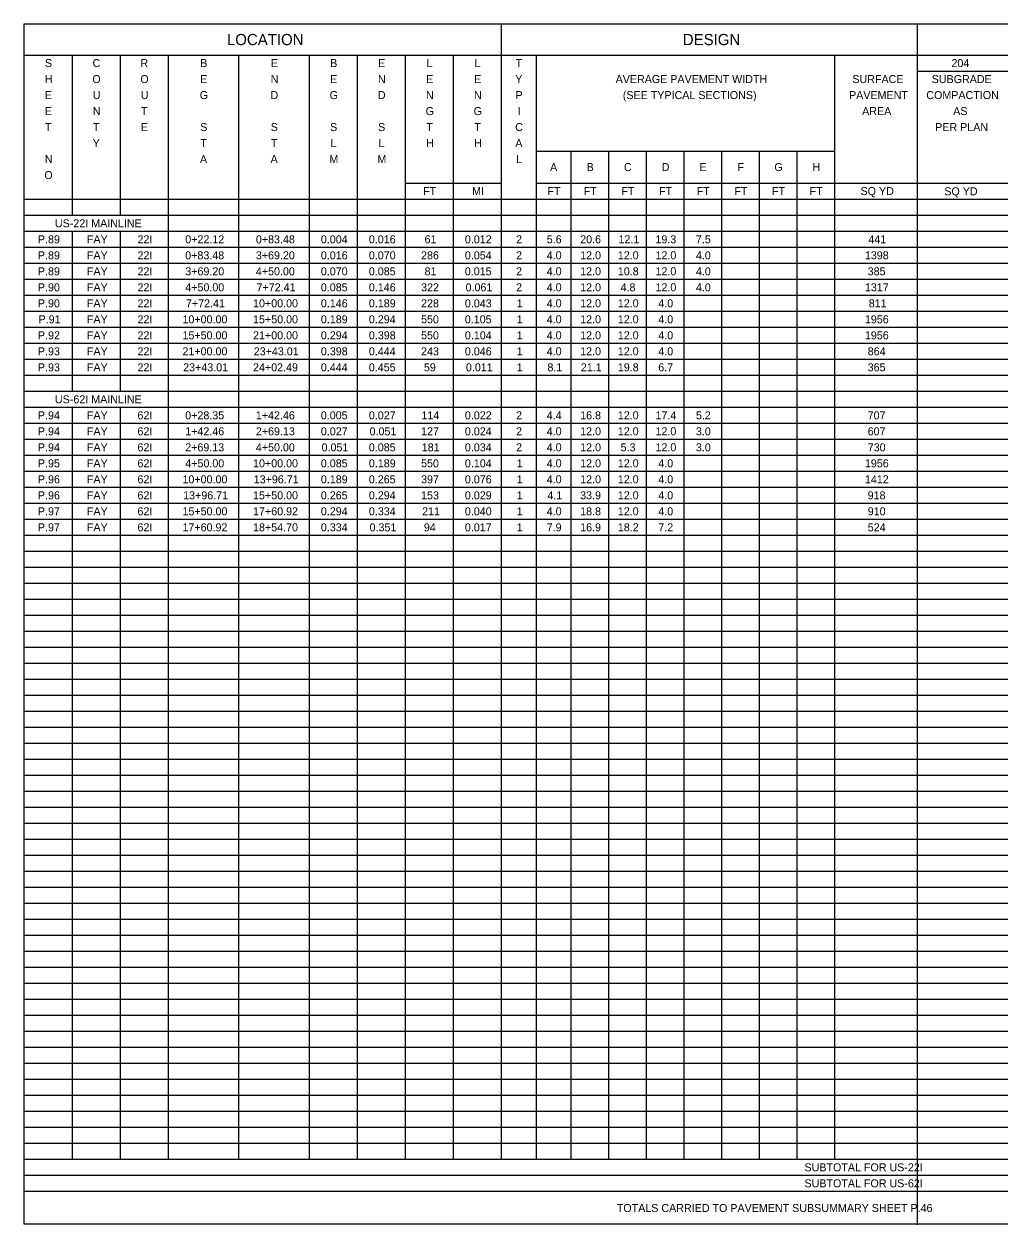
# Model space of a CAD drawing. Extents: x 12522 to 13018, y 1124 to 1902.
# Drawn here: x 12797.22 to 12814.3, y 1708.07 to 1729.09 of the extents above; entities that cross this region are included whole.
import ezdxf

# ---------------------------------------------------------------- set-up
doc = ezdxf.new("R2010")
doc.units = 0
for name, color, linetype in [('SC_Scratch1', 7, 'Continuous'), ('SH_Data', 7, 'Continuous'), ('SH_Text', 7, 'Continuous')]:
    doc.layers.add(name, color=color, linetype=linetype)

msp = doc.modelspace()

# ---------------------------------------------------------------- linework, layer by layer
at = {"layer": 'SC_Scratch1'}
msp.add_lwpolyline([(12797.224, 1729.086), (12827.724, 1729.086), (12827.724, 1708.086), (12797.224, 1708.086)], close=True, dxfattribs=at)
at = {"layer": 'SH_Data'}
for p, q in [((12805.575, 1729.086), (12805.575, 1709.222)), ((12812.855, 1729.086), (12812.855, 1708.069)), ((12797.224, 1728.542), (12827.678, 1728.542)), ((12798.064, 1728.542), (12798.064, 1725.742)), ((12798.904, 1728.542), (12798.904, 1725.742)), ((12799.744, 1728.542), (12799.744, 1709.222)), ((12800.979, 1728.542), (12800.979, 1709.222)), ((12802.215, 1728.542), (12802.215, 1709.222)), ((12803.055, 1728.542), (12803.055, 1709.222)), ((12803.895, 1728.542), (12803.895, 1709.222)), ((12804.735, 1728.542), (12804.735, 1709.222)), ((12806.184, 1728.542), (12806.184, 1709.222)), ((12811.405, 1728.542), (12811.405, 1709.222)), ((12812.855, 1728.262), (12827.678, 1728.262)), ((12806.184, 1726.862), (12811.405, 1726.862)), ((12806.794, 1726.862), (12806.794, 1709.222)), ((12807.452, 1726.862), (12807.452, 1709.222)), ((12808.111, 1726.862), (12808.111, 1709.222)), ((12808.77, 1726.862), (12808.77, 1709.222)), ((12809.429, 1726.862), (12809.429, 1709.222)), ((12810.088, 1726.862), (12810.088, 1709.222)), ((12810.747, 1726.862), (12810.747, 1709.222)), ((12803.895, 1726.302), (12805.575, 1726.302)), ((12806.184, 1726.302), (12827.678, 1726.302)), ((12797.224, 1726.022), (12827.678, 1726.022)), ((12797.224, 1725.742), (12827.678, 1725.742)), ((12797.224, 1725.462), (12827.678, 1725.462)), ((12798.064, 1725.462), (12798.064, 1722.662)), ((12798.904, 1725.462), (12798.904, 1722.662)), ((12797.224, 1725.182), (12827.678, 1725.182)), ((12797.224, 1724.902), (12827.678, 1724.902)), ((12797.224, 1724.622), (12827.678, 1724.622)), ((12797.224, 1724.342), (12827.678, 1724.342)), ((12797.224, 1724.062), (12827.678, 1724.062)), ((12797.224, 1723.782), (12827.678, 1723.782)), ((12797.224, 1723.502), (12827.678, 1723.502)), ((12797.224, 1723.222), (12827.678, 1723.222)), ((12797.224, 1722.942), (12827.678, 1722.942)), ((12797.224, 1722.662), (12827.678, 1722.662)), ((12797.224, 1722.382), (12827.678, 1722.382)), ((12798.064, 1722.382), (12798.064, 1709.222)), ((12798.904, 1722.382), (12798.904, 1709.222)), ((12797.224, 1722.102), (12827.678, 1722.102)), ((12797.224, 1721.822), (12827.678, 1721.822)), ((12797.224, 1721.542), (12827.678, 1721.542)), ((12797.224, 1721.262), (12827.678, 1721.262)), ((12797.224, 1720.982), (12827.678, 1720.982)), ((12797.224, 1720.702), (12827.678, 1720.702)), ((12797.224, 1720.422), (12827.678, 1720.422)), ((12797.224, 1720.142), (12827.678, 1720.142)), ((12797.224, 1719.862), (12827.678, 1719.862)), ((12797.224, 1719.582), (12827.678, 1719.582)), ((12797.224, 1719.302), (12827.678, 1719.302)), ((12797.224, 1719.022), (12827.678, 1719.022)), ((12797.224, 1718.742), (12827.678, 1718.742)), ((12797.224, 1718.462), (12827.678, 1718.462)), ((12797.224, 1718.182), (12827.678, 1718.182)), ((12797.224, 1717.902), (12827.678, 1717.902)), ((12797.224, 1717.622), (12827.678, 1717.622)), ((12797.224, 1717.342), (12827.678, 1717.342)), ((12797.224, 1717.062), (12827.678, 1717.062)), ((12797.224, 1716.782), (12827.678, 1716.782)), ((12797.224, 1716.502), (12827.678, 1716.502)), ((12797.224, 1716.222), (12827.678, 1716.222)), ((12797.224, 1715.942), (12827.678, 1715.942)), ((12797.224, 1715.662), (12827.678, 1715.662)), ((12797.224, 1715.382), (12827.678, 1715.382)), ((12797.224, 1715.102), (12827.678, 1715.102)), ((12797.224, 1714.822), (12827.678, 1714.822)), ((12797.224, 1714.542), (12827.678, 1714.542)), ((12797.224, 1714.262), (12827.678, 1714.262)), ((12797.224, 1713.982), (12827.678, 1713.982)), ((12797.224, 1713.702), (12827.678, 1713.702)), ((12797.224, 1713.422), (12827.678, 1713.422)), ((12797.224, 1713.142), (12827.678, 1713.142)), ((12797.224, 1712.862), (12827.678, 1712.862)), ((12797.224, 1712.582), (12827.678, 1712.582)), ((12797.224, 1712.302), (12827.678, 1712.302)), ((12797.224, 1712.022), (12827.678, 1712.022)), ((12797.224, 1711.742), (12827.678, 1711.742)), ((12797.224, 1711.462), (12827.678, 1711.462)), ((12797.224, 1711.182), (12827.678, 1711.182)), ((12797.224, 1710.902), (12827.678, 1710.902)), ((12797.224, 1710.622), (12827.678, 1710.622)), ((12797.224, 1710.342), (12827.678, 1710.342)), ((12797.224, 1710.062), (12827.678, 1710.062)), ((12797.224, 1709.782), (12827.678, 1709.782)), ((12797.224, 1709.502), (12827.678, 1709.502)), ((12797.224, 1709.222), (12827.678, 1709.222)), ((12797.224, 1708.942), (12827.678, 1708.942)), ((12797.224, 1708.662), (12827.678, 1708.662))]:
    msp.add_line(p, q, dxfattribs=at)

# ---------------------------------------------------------------- texts
at = {"layer": 'SH_Text'}
for s, height, p in [('LOCATION', 0.196, (12800.775, 1728.716)), ('DESIGN', 0.196, (12808.752, 1728.716)), ('S', 0.14, (12797.59, 1728.332)), ('C', 0.14, (12798.424, 1728.332)), ('R', 0.14, (12799.262, 1728.332)), ('B', 0.14, (12800.308, 1728.332)), ('E', 0.14, (12801.543, 1728.332)), ('B', 0.14, (12802.581, 1728.332)), ('E', 0.14, (12803.421, 1728.332)), ('L', 0.14, (12804.269, 1728.332)), ('L', 0.14, (12805.109, 1728.332)), ('T', 0.14, (12805.827, 1728.332)), ('204', 0.14, (12813.453, 1728.332)), ('H', 0.14, (12797.588, 1728.052)), ('O', 0.14, (12798.42, 1728.052)), ('O', 0.14, (12799.26, 1728.052)), ('E', 0.14, (12800.308, 1728.052)), ('N', 0.14, (12801.541, 1728.052)), ('E', 0.14, (12802.581, 1728.052)), ('N', 0.14, (12803.418, 1728.052)), ('E', 0.14, (12804.261, 1728.052)), ('E', 0.14, (12805.101, 1728.052)), ('Y', 0.14, (12805.821, 1728.052)), ('AVERAGE PAVEMENT WIDTH', 0.14, (12807.576, 1728.052)), ('SURFACE', 0.14, (12811.719, 1728.052)), ('SUBGRADE', 0.14, (12813.107, 1728.052)), ('E', 0.14, (12797.59, 1727.772)), ('U', 0.14, (12798.428, 1727.772)), ('U', 0.14, (12799.268, 1727.772)), ('G', 0.14, (12800.299, 1727.772)), ('D', 0.14, (12801.538, 1727.772)), ('G', 0.14, (12802.572, 1727.772)), ('D', 0.14, (12803.416, 1727.772)), ('N', 0.14, (12804.258, 1727.772)), ('N', 0.14, (12805.098, 1727.772)), ('P', 0.14, (12805.825, 1727.772)), ('(SEE TYPICAL SECTIONS)', 0.14, (12807.702, 1727.772)), ('PAVEMENT', 0.14, (12811.661, 1727.772)), ('COMPACTION', 0.14, (12813.013, 1727.772)), ('E', 0.14, (12797.59, 1727.492)), ('N', 0.14, (12798.428, 1727.492)), ('T', 0.14, (12799.272, 1727.492)), ('G', 0.14, (12804.252, 1727.492)), ('G', 0.14, (12805.092, 1727.492)), ('I', 0.14, (12805.863, 1727.492)), ('AREA', 0.14, (12811.89, 1727.492)), ('AS', 0.14, (12813.483, 1727.492)), ('T', 0.14, (12797.592, 1727.212)), ('T', 0.14, (12798.432, 1727.212)), ('E', 0.14, (12799.27, 1727.212)), ('S', 0.14, (12800.308, 1727.212)), ('S', 0.14, (12801.543, 1727.212)), ('S', 0.14, (12802.581, 1727.212)), ('S', 0.14, (12803.421, 1727.212)), ('T', 0.14, (12804.263, 1727.212)), ('T', 0.14, (12805.103, 1727.212)), ('C', 0.14, (12805.819, 1727.212)), ('PER PLAN', 0.14, (12813.168, 1727.212)), ('Y', 0.14, (12798.426, 1726.932)), ('T', 0.14, (12800.31, 1726.932)), ('T', 0.14, (12801.545, 1726.932)), ('L', 0.14, (12802.589, 1726.932)), ('L', 0.14, (12803.429, 1726.932)), ('H', 0.14, (12804.258, 1726.932)), ('H', 0.14, (12805.098, 1726.932)), ('A', 0.14, (12805.821, 1726.932)), ('N', 0.14, (12797.588, 1726.652)), ('A', 0.14, (12800.303, 1726.652)), ('A', 0.14, (12801.538, 1726.652)), ('M', 0.14, (12802.568, 1726.652)), ('M', 0.14, (12803.408, 1726.652)), ('L', 0.14, (12805.834, 1726.652)), ('O', 0.14, (12797.58, 1726.372)), ('A', 0.14, (12806.43, 1726.512)), ('B', 0.14, (12807.069, 1726.512)), ('C', 0.14, (12807.722, 1726.512)), ('D', 0.14, (12808.382, 1726.512)), ('E', 0.14, (12809.045, 1726.512)), ('F', 0.14, (12809.709, 1726.512)), ('G', 0.14, (12810.354, 1726.512)), ('H', 0.14, (12811.02, 1726.512)), ('FT', 0.14, (12804.209, 1726.092)), ('MI', 0.14, (12805.065, 1726.092)), ('FT', 0.14, (12806.383, 1726.092)), ('FT', 0.14, (12807.017, 1726.092)), ('FT', 0.14, (12807.676, 1726.092)), ('FT', 0.14, (12808.335, 1726.092)), ('FT', 0.14, (12808.994, 1726.092)), ('FT', 0.14, (12809.653, 1726.092)), ('FT', 0.14, (12810.311, 1726.092)), ('FT', 0.14, (12810.97, 1726.092)), ('SQ YD', 0.14, (12811.862, 1726.092)), ('SQ YD', 0.14, (12813.328, 1726.088)), ('US-22I MAINLINE', 0.14, (12797.765, 1725.528)), ('P.89', 0.14, (12797.467, 1725.248)), ('FAY', 0.14, (12798.325, 1725.248)), ('22I', 0.14, (12799.21, 1725.248)), ('0+22.12', 0.14, (12800.046, 1725.248)), ('0+83.48', 0.14, (12801.281, 1725.248)), ('0.004', 0.14, (12802.419, 1725.248)), ('0.016', 0.14, (12803.259, 1725.248)), ('61', 0.14, (12804.233, 1725.248)), ('0.012', 0.14, (12804.939, 1725.248)), ('2', 0.14, (12805.835, 1725.248)), ('5.6', 0.14, (12806.371, 1725.248)), ('20.6', 0.14, (12806.956, 1725.248)), ('12.1', 0.14, (12807.627, 1725.248)), ('19.3', 0.14, (12808.273, 1725.248)), ('7.5', 0.14, (12808.981, 1725.248)), ('441', 0.14, (12811.999, 1725.248)), ('P.89', 0.14, (12797.467, 1724.968)), ('FAY', 0.14, (12798.325, 1724.968)), ('22I', 0.14, (12799.21, 1724.968)), ('0+83.48', 0.14, (12800.045, 1724.968)), ('3+69.20', 0.14, (12801.281, 1724.968)), ('0.016', 0.14, (12802.419, 1724.968)), ('0.070', 0.14, (12803.259, 1724.968)), ('286', 0.14, (12804.172, 1724.968)), ('0.054', 0.14, (12804.939, 1724.968)), ('2', 0.14, (12805.835, 1724.968)), ('4.0', 0.14, (12806.371, 1724.968)), ('12.0', 0.14, (12806.956, 1724.968)), ('12.0', 0.14, (12807.615, 1724.968)), ('12.0', 0.14, (12808.274, 1724.968)), ('4.0', 0.14, (12808.981, 1724.968)), ('1398', 0.14, (12811.938, 1724.968)), ('P.89', 0.14, (12797.467, 1724.688)), ('FAY', 0.14, (12798.325, 1724.688)), ('22I', 0.14, (12799.21, 1724.688)), ('3+69.20', 0.14, (12800.046, 1724.688)), ('4+50.00', 0.14, (12801.281, 1724.688)), ('0.070', 0.14, (12802.419, 1724.688)), ('0.085', 0.14, (12803.258, 1724.688)), ('81', 0.14, (12804.233, 1724.688)), ('0.015', 0.14, (12804.938, 1724.688)), ('2', 0.14, (12805.835, 1724.688)), ('4.0', 0.14, (12806.371, 1724.688)), ('12.0', 0.14, (12806.956, 1724.688)), ('10.8', 0.14, (12807.615, 1724.688)), ('12.0', 0.14, (12808.274, 1724.688)), ('4.0', 0.14, (12808.981, 1724.688)), ('385', 0.14, (12811.987, 1724.688)), ('P.90', 0.14, (12797.467, 1724.408)), ('FAY', 0.14, (12798.325, 1724.408)), ('22I', 0.14, (12799.21, 1724.408)), ('4+50.00', 0.14, (12800.046, 1724.408)), ('7+72.41', 0.14, (12801.293, 1724.408)), ('0.085', 0.14, (12802.418, 1724.408)), ('0.146', 0.14, (12803.259, 1724.408)), ('322', 0.14, (12804.173, 1724.408)), ('0.061', 0.14, (12804.951, 1724.408)), ('2', 0.14, (12805.835, 1724.408)), ('4.0', 0.14, (12806.371, 1724.408)), ('12.0', 0.14, (12806.956, 1724.408)), ('4.8', 0.14, (12807.663, 1724.408)), ('12.0', 0.14, (12808.274, 1724.408)), ('4.0', 0.14, (12808.981, 1724.408)), ('1317', 0.14, (12811.938, 1724.408)), ('P.90', 0.14, (12797.467, 1724.128)), ('FAY', 0.14, (12798.325, 1724.128)), ('22I', 0.14, (12799.21, 1724.128)), ('7+72.41', 0.14, (12800.058, 1724.128)), ('10+00.00', 0.14, (12801.232, 1724.128)), ('0.146', 0.14, (12802.419, 1724.128)), ('0.189', 0.14, (12803.259, 1724.128)), ('228', 0.14, (12804.172, 1724.128)), ('0.043', 0.14, (12804.939, 1724.128)), ('1', 0.14, (12805.847, 1724.128)), ('4.0', 0.14, (12806.371, 1724.128)), ('12.0', 0.14, (12806.956, 1724.128)), ('12.0', 0.14, (12807.615, 1724.128)), ('4.0', 0.14, (12808.323, 1724.128)), ('811', 0.14, (12812.006, 1724.128)), ('P.91', 0.14, (12797.479, 1723.848)), ('FAY', 0.14, (12798.325, 1723.848)), ('22I', 0.14, (12799.21, 1723.848)), ('10+00.00', 0.14, (12799.997, 1723.848)), ('15+50.00', 0.14, (12801.232, 1723.848)), ('0.189', 0.14, (12802.419, 1723.848)), ('0.294', 0.14, (12803.259, 1723.848)), ('550', 0.14, (12804.172, 1723.848)), ('0.105', 0.14, (12804.938, 1723.848)), ('1', 0.14, (12805.847, 1723.848)), ('4.0', 0.14, (12806.371, 1723.848)), ('12.0', 0.14, (12806.956, 1723.848)), ('12.0', 0.14, (12807.615, 1723.848)), ('4.0', 0.14, (12808.323, 1723.848)), ('1956', 0.14, (12811.938, 1723.848)), ('P.92', 0.14, (12797.468, 1723.568)), ('FAY', 0.14, (12798.325, 1723.568)), ('22I', 0.14, (12799.21, 1723.568)), ('15+50.00', 0.14, (12799.997, 1723.568)), ('21+00.00', 0.14, (12801.232, 1723.568)), ('0.294', 0.14, (12802.419, 1723.568)), ('0.398', 0.14, (12803.259, 1723.568)), ('550', 0.14, (12804.172, 1723.568)), ('0.104', 0.14, (12804.939, 1723.568)), ('1', 0.14, (12805.847, 1723.568)), ('4.0', 0.14, (12806.371, 1723.568)), ('12.0', 0.14, (12806.956, 1723.568)), ('12.0', 0.14, (12807.615, 1723.568)), ('4.0', 0.14, (12808.323, 1723.568)), ('1956', 0.14, (12811.938, 1723.568)), ('P.93', 0.14, (12797.467, 1723.288)), ('FAY', 0.14, (12798.325, 1723.288)), ('22I', 0.14, (12799.21, 1723.288)), ('21+00.00', 0.14, (12799.997, 1723.288)), ('23+43.01', 0.14, (12801.244, 1723.288)), ('0.398', 0.14, (12802.419, 1723.288)), ('0.444', 0.14, (12803.259, 1723.288)), ('243', 0.14, (12804.172, 1723.288)), ('0.046', 0.14, (12804.939, 1723.288)), ('1', 0.14, (12805.847, 1723.288)), ('4.0', 0.14, (12806.371, 1723.288)), ('12.0', 0.14, (12806.956, 1723.288)), ('12.0', 0.14, (12807.615, 1723.288)), ('4.0', 0.14, (12808.323, 1723.288)), ('864', 0.14, (12811.988, 1723.288)), ('P.93', 0.14, (12797.467, 1723.008)), ('FAY', 0.14, (12798.325, 1723.008)), ('22I', 0.14, (12799.21, 1723.008)), ('23+43.01', 0.14, (12800.009, 1723.008)), ('24+02.49', 0.14, (12801.232, 1723.008)), ('0.444', 0.14, (12802.419, 1723.008)), ('0.455', 0.14, (12803.258, 1723.008)), ('59', 0.14, (12804.221, 1723.008)), ('0.011', 0.14, (12804.957, 1723.008)), ('1', 0.14, (12805.847, 1723.008)), ('8.1', 0.14, (12806.383, 1723.008)), ('21.1', 0.14, (12806.968, 1723.008)), ('19.8', 0.14, (12807.615, 1723.008)), ('6.7', 0.14, (12808.322, 1723.008)), ('365', 0.14, (12811.987, 1723.008)), ('US-62I MAINLINE', 0.14, (12797.765, 1722.448)), ('P.94', 0.14, (12797.467, 1722.168)), ('FAY', 0.14, (12798.325, 1722.168)), ('62I', 0.14, (12799.21, 1722.168)), ('0+28.35', 0.14, (12800.045, 1722.168)), ('1+42.46', 0.14, (12801.281, 1722.168)), ('0.005', 0.14, (12802.418, 1722.168)), ('0.027', 0.14, (12803.259, 1722.168)), ('114', 0.14, (12804.179, 1722.168)), ('0.022', 0.14, (12804.939, 1722.168)), ('2', 0.14, (12805.835, 1722.168)), ('4.4', 0.14, (12806.371, 1722.168)), ('16.8', 0.14, (12806.956, 1722.168)), ('12.0', 0.14, (12807.615, 1722.168)), ('17.4', 0.14, (12808.274, 1722.168)), ('5.2', 0.14, (12808.982, 1722.168)), ('707', 0.14, (12811.987, 1722.168)), ('P.94', 0.14, (12797.467, 1721.888)), ('FAY', 0.14, (12798.325, 1721.888)), ('62I', 0.14, (12799.21, 1721.888)), ('1+42.46', 0.14, (12800.045, 1721.888)), ('2+69.13', 0.14, (12801.281, 1721.888)), ('0.027', 0.14, (12802.419, 1721.888)), ('0.051', 0.14, (12803.271, 1721.888)), ('127', 0.14, (12804.172, 1721.888)), ('0.024', 0.14, (12804.939, 1721.888)), ('2', 0.14, (12805.835, 1721.888)), ('4.0', 0.14, (12806.371, 1721.888)), ('12.0', 0.14, (12806.956, 1721.888)), ('12.0', 0.14, (12807.615, 1721.888)), ('12.0', 0.14, (12808.274, 1721.888)), ('3.0', 0.14, (12808.981, 1721.888)), ('607', 0.14, (12811.987, 1721.888)), ('P.94', 0.14, (12797.467, 1721.608)), ('FAY', 0.14, (12798.325, 1721.608)), ('62I', 0.14, (12799.21, 1721.608)), ('2+69.13', 0.14, (12800.045, 1721.608)), ('4+50.00', 0.14, (12801.281, 1721.608)), ('0.051', 0.14, (12802.431, 1721.608)), ('0.085', 0.14, (12803.258, 1721.608)), ('181', 0.14, (12804.184, 1721.608)), ('0.034', 0.14, (12804.939, 1721.608)), ('2', 0.14, (12805.835, 1721.608)), ('4.0', 0.14, (12806.371, 1721.608)), ('12.0', 0.14, (12806.956, 1721.608)), ('5.3', 0.14, (12807.664, 1721.608)), ('12.0', 0.14, (12808.274, 1721.608)), ('3.0', 0.14, (12808.981, 1721.608)), ('730', 0.14, (12811.988, 1721.608)), ('P.95', 0.14, (12797.467, 1721.328)), ('FAY', 0.14, (12798.325, 1721.328)), ('62I', 0.14, (12799.21, 1721.328)), ('4+50.00', 0.14, (12800.046, 1721.328)), ('10+00.00', 0.14, (12801.232, 1721.328)), ('0.085', 0.14, (12802.418, 1721.328)), ('0.189', 0.14, (12803.259, 1721.328)), ('550', 0.14, (12804.172, 1721.328)), ('0.104', 0.14, (12804.939, 1721.328)), ('1', 0.14, (12805.847, 1721.328)), ('4.0', 0.14, (12806.371, 1721.328)), ('12.0', 0.14, (12806.956, 1721.328)), ('12.0', 0.14, (12807.615, 1721.328)), ('4.0', 0.14, (12808.323, 1721.328)), ('1956', 0.14, (12811.938, 1721.328)), ('P.96', 0.14, (12797.467, 1721.048)), ('FAY', 0.14, (12798.325, 1721.048)), ('62I', 0.14, (12799.21, 1721.048)), ('10+00.00', 0.14, (12799.997, 1721.048)), ('13+96.71', 0.14, (12801.244, 1721.048)), ('0.189', 0.14, (12802.419, 1721.048)), ('0.265', 0.14, (12803.258, 1721.048)), ('397', 0.14, (12804.172, 1721.048)), ('0.076', 0.14, (12804.939, 1721.048)), ('1', 0.14, (12805.847, 1721.048)), ('4.0', 0.14, (12806.371, 1721.048)), ('12.0', 0.14, (12806.956, 1721.048)), ('12.0', 0.14, (12807.615, 1721.048)), ('4.0', 0.14, (12808.323, 1721.048)), ('1412', 0.14, (12811.939, 1721.048)), ('P.96', 0.14, (12797.467, 1720.768)), ('FAY', 0.14, (12798.325, 1720.768)), ('62I', 0.14, (12799.21, 1720.768)), ('13+96.71', 0.14, (12800.009, 1720.768)), ('15+50.00', 0.14, (12801.232, 1720.768)), ('0.265', 0.14, (12802.418, 1720.768)), ('0.294', 0.14, (12803.259, 1720.768)), ('153', 0.14, (12804.172, 1720.768)), ('0.029', 0.14, (12804.939, 1720.768)), ('1', 0.14, (12805.847, 1720.768)), ('4.1', 0.14, (12806.383, 1720.768)), ('33.9', 0.14, (12806.956, 1720.768)), ('12.0', 0.14, (12807.615, 1720.768)), ('4.0', 0.14, (12808.323, 1720.768)), ('918', 0.14, (12811.987, 1720.768)), ('P.97', 0.14, (12797.467, 1720.488)), ('FAY', 0.14, (12798.325, 1720.488)), ('62I', 0.14, (12799.21, 1720.488)), ('15+50.00', 0.14, (12799.997, 1720.488)), ('17+60.92', 0.14, (12801.232, 1720.488)), ('0.294', 0.14, (12802.419, 1720.488)), ('0.334', 0.14, (12803.259, 1720.488)), ('211', 0.14, (12804.191, 1720.488)), ('0.040', 0.14, (12804.939, 1720.488)), ('1', 0.14, (12805.847, 1720.488)), ('4.0', 0.14, (12806.371, 1720.488)), ('18.8', 0.14, (12806.956, 1720.488)), ('12.0', 0.14, (12807.615, 1720.488)), ('4.0', 0.14, (12808.323, 1720.488)), ('910', 0.14, (12811.988, 1720.488)), ('P.97', 0.14, (12797.467, 1720.208)), ('FAY', 0.14, (12798.325, 1720.208)), ('62I', 0.14, (12799.21, 1720.208)), ('17+60.92', 0.14, (12799.997, 1720.208)), ('18+54.70', 0.14, (12801.232, 1720.208)), ('0.334', 0.14, (12802.419, 1720.208)), ('0.351', 0.14, (12803.271, 1720.208)), ('94', 0.14, (12804.221, 1720.208)), ('0.017', 0.14, (12804.939, 1720.208)), ('1', 0.14, (12805.847, 1720.208)), ('7.9', 0.14, (12806.37, 1720.208)), ('16.9', 0.14, (12806.956, 1720.208)), ('18.2', 0.14, (12807.615, 1720.208)), ('7.2', 0.14, (12808.323, 1720.208)), ('524', 0.14, (12811.988, 1720.208)), ('SUBTOTAL FOR US-22I', 0.14, (12810.881, 1709.008)), ('SUBTOTAL FOR US-62I', 0.14, (12810.881, 1708.728)), ('TOTALS CARRIED TO PAVEMENT SUBSUMMARY SHEET P.46', 0.14, (12807.597, 1708.296))]:
    msp.add_text(s, height=height, dxfattribs=at).set_placement(p)

doc.saveas('drawing.dxf')
